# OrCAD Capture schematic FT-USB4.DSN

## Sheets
1 INDEX: title: 01-INDEX; rev: 1.0
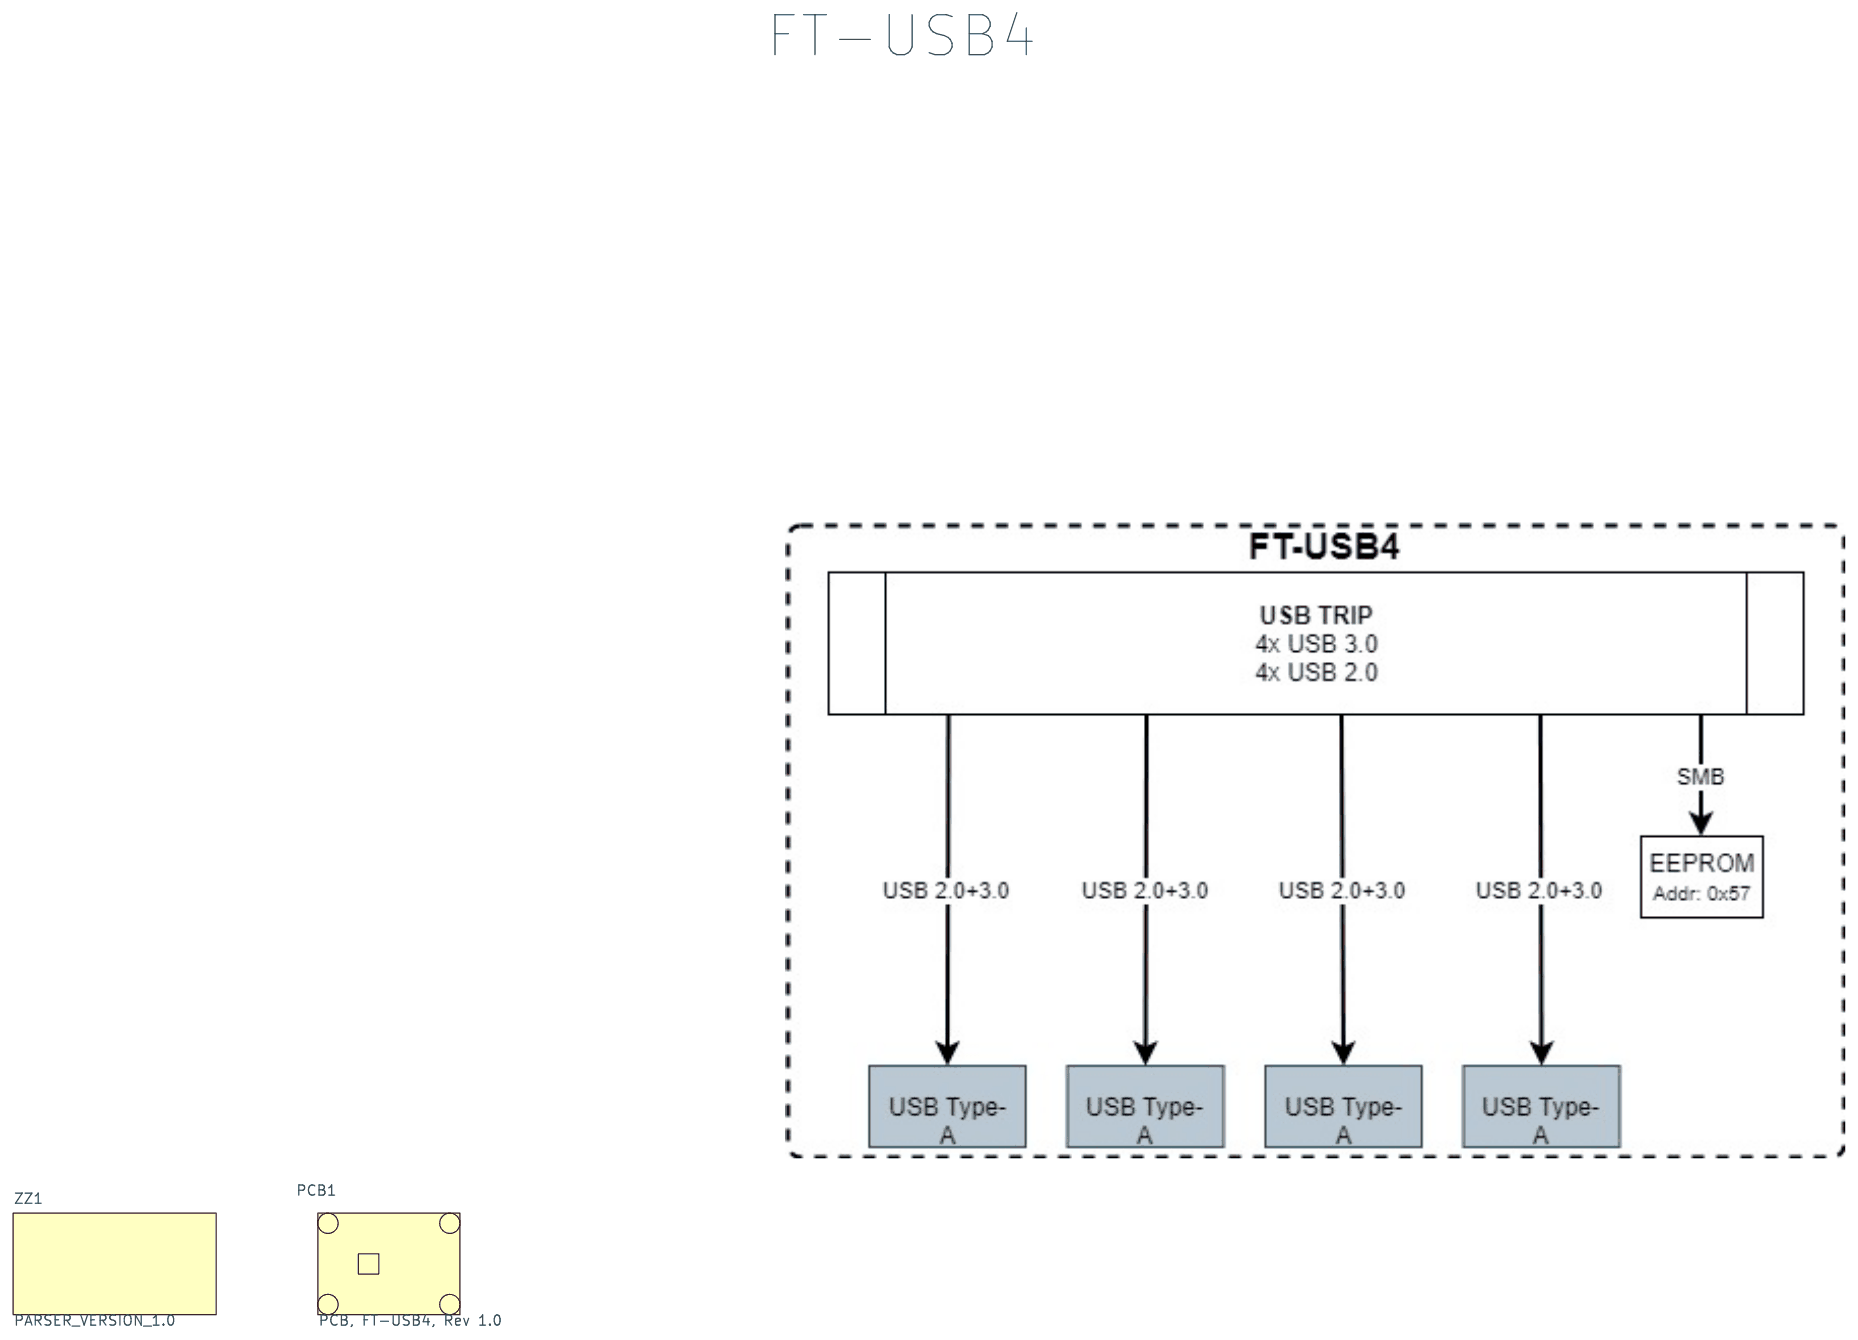
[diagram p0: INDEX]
2 TRIP: size A; title: 02-TRIP
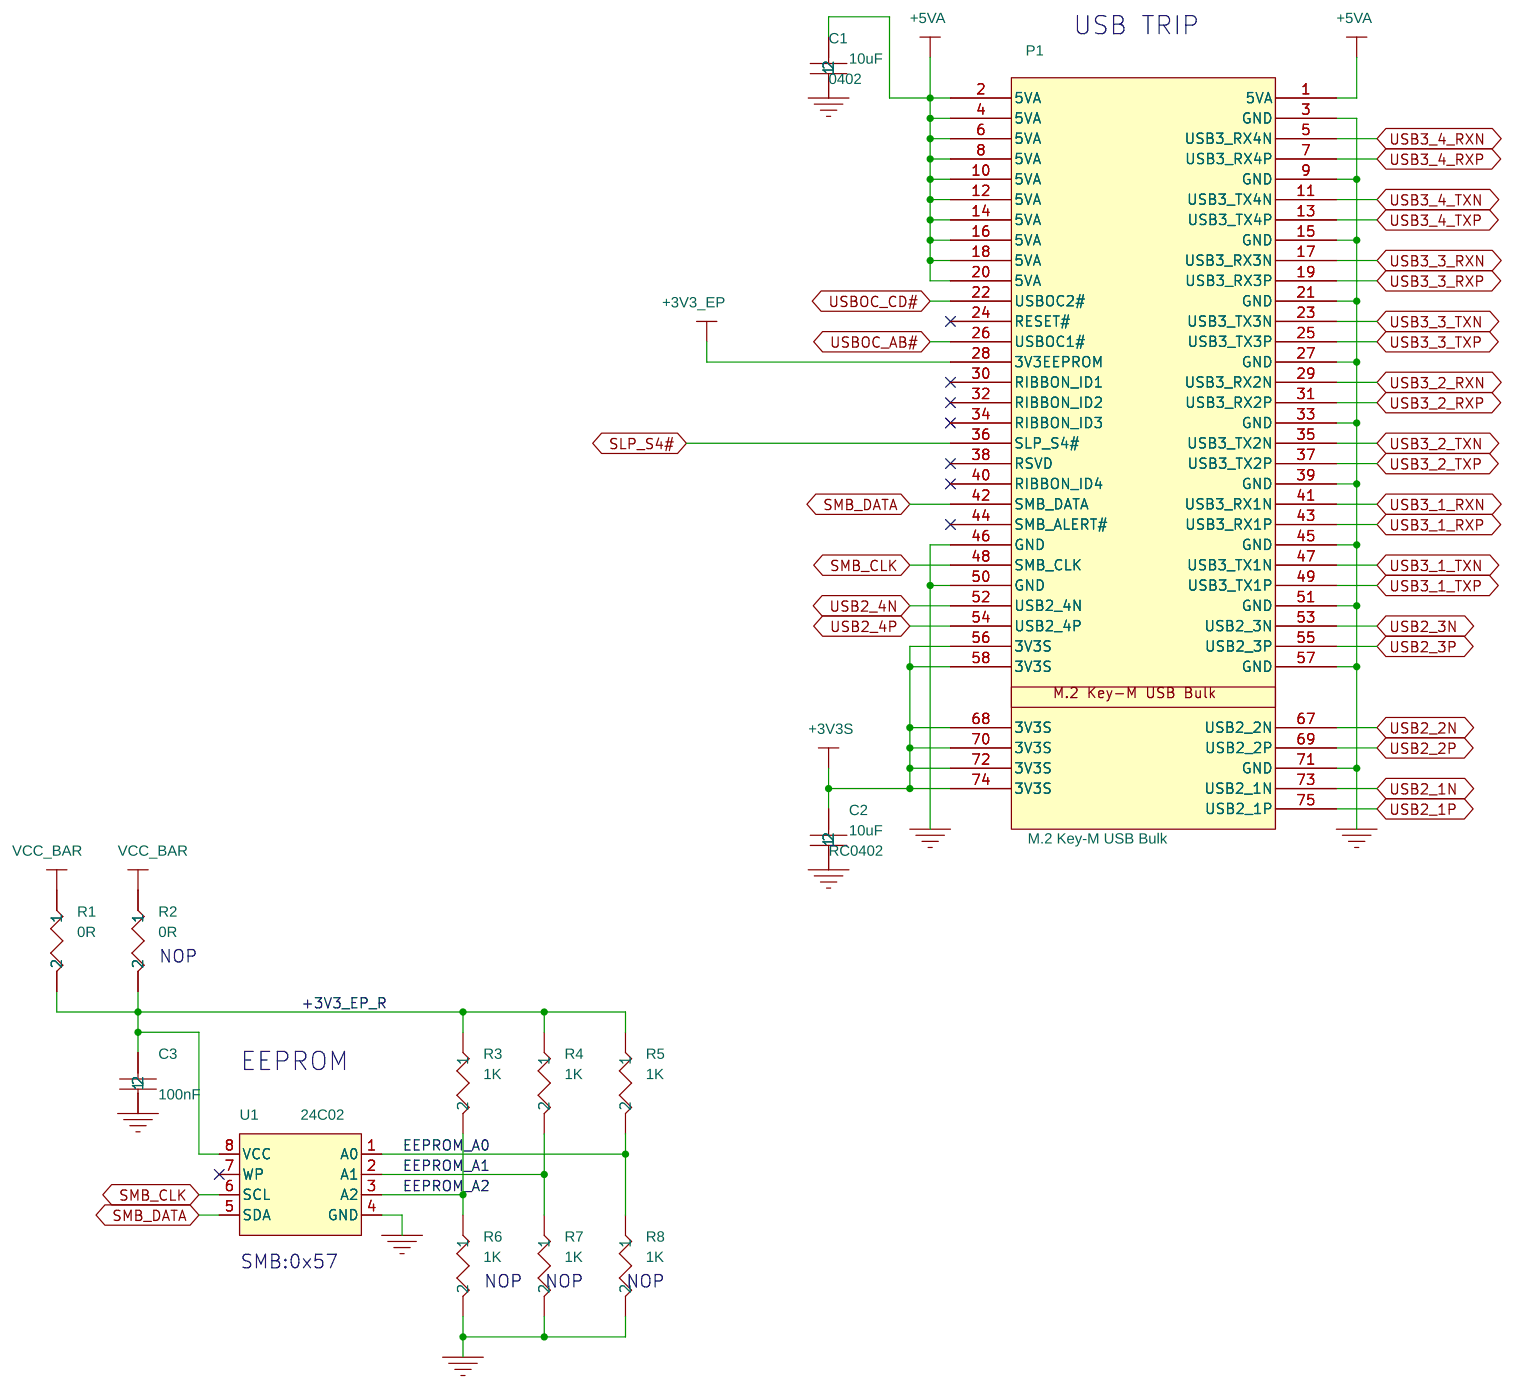
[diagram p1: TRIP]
3 USB: size A3; title: 03-USB
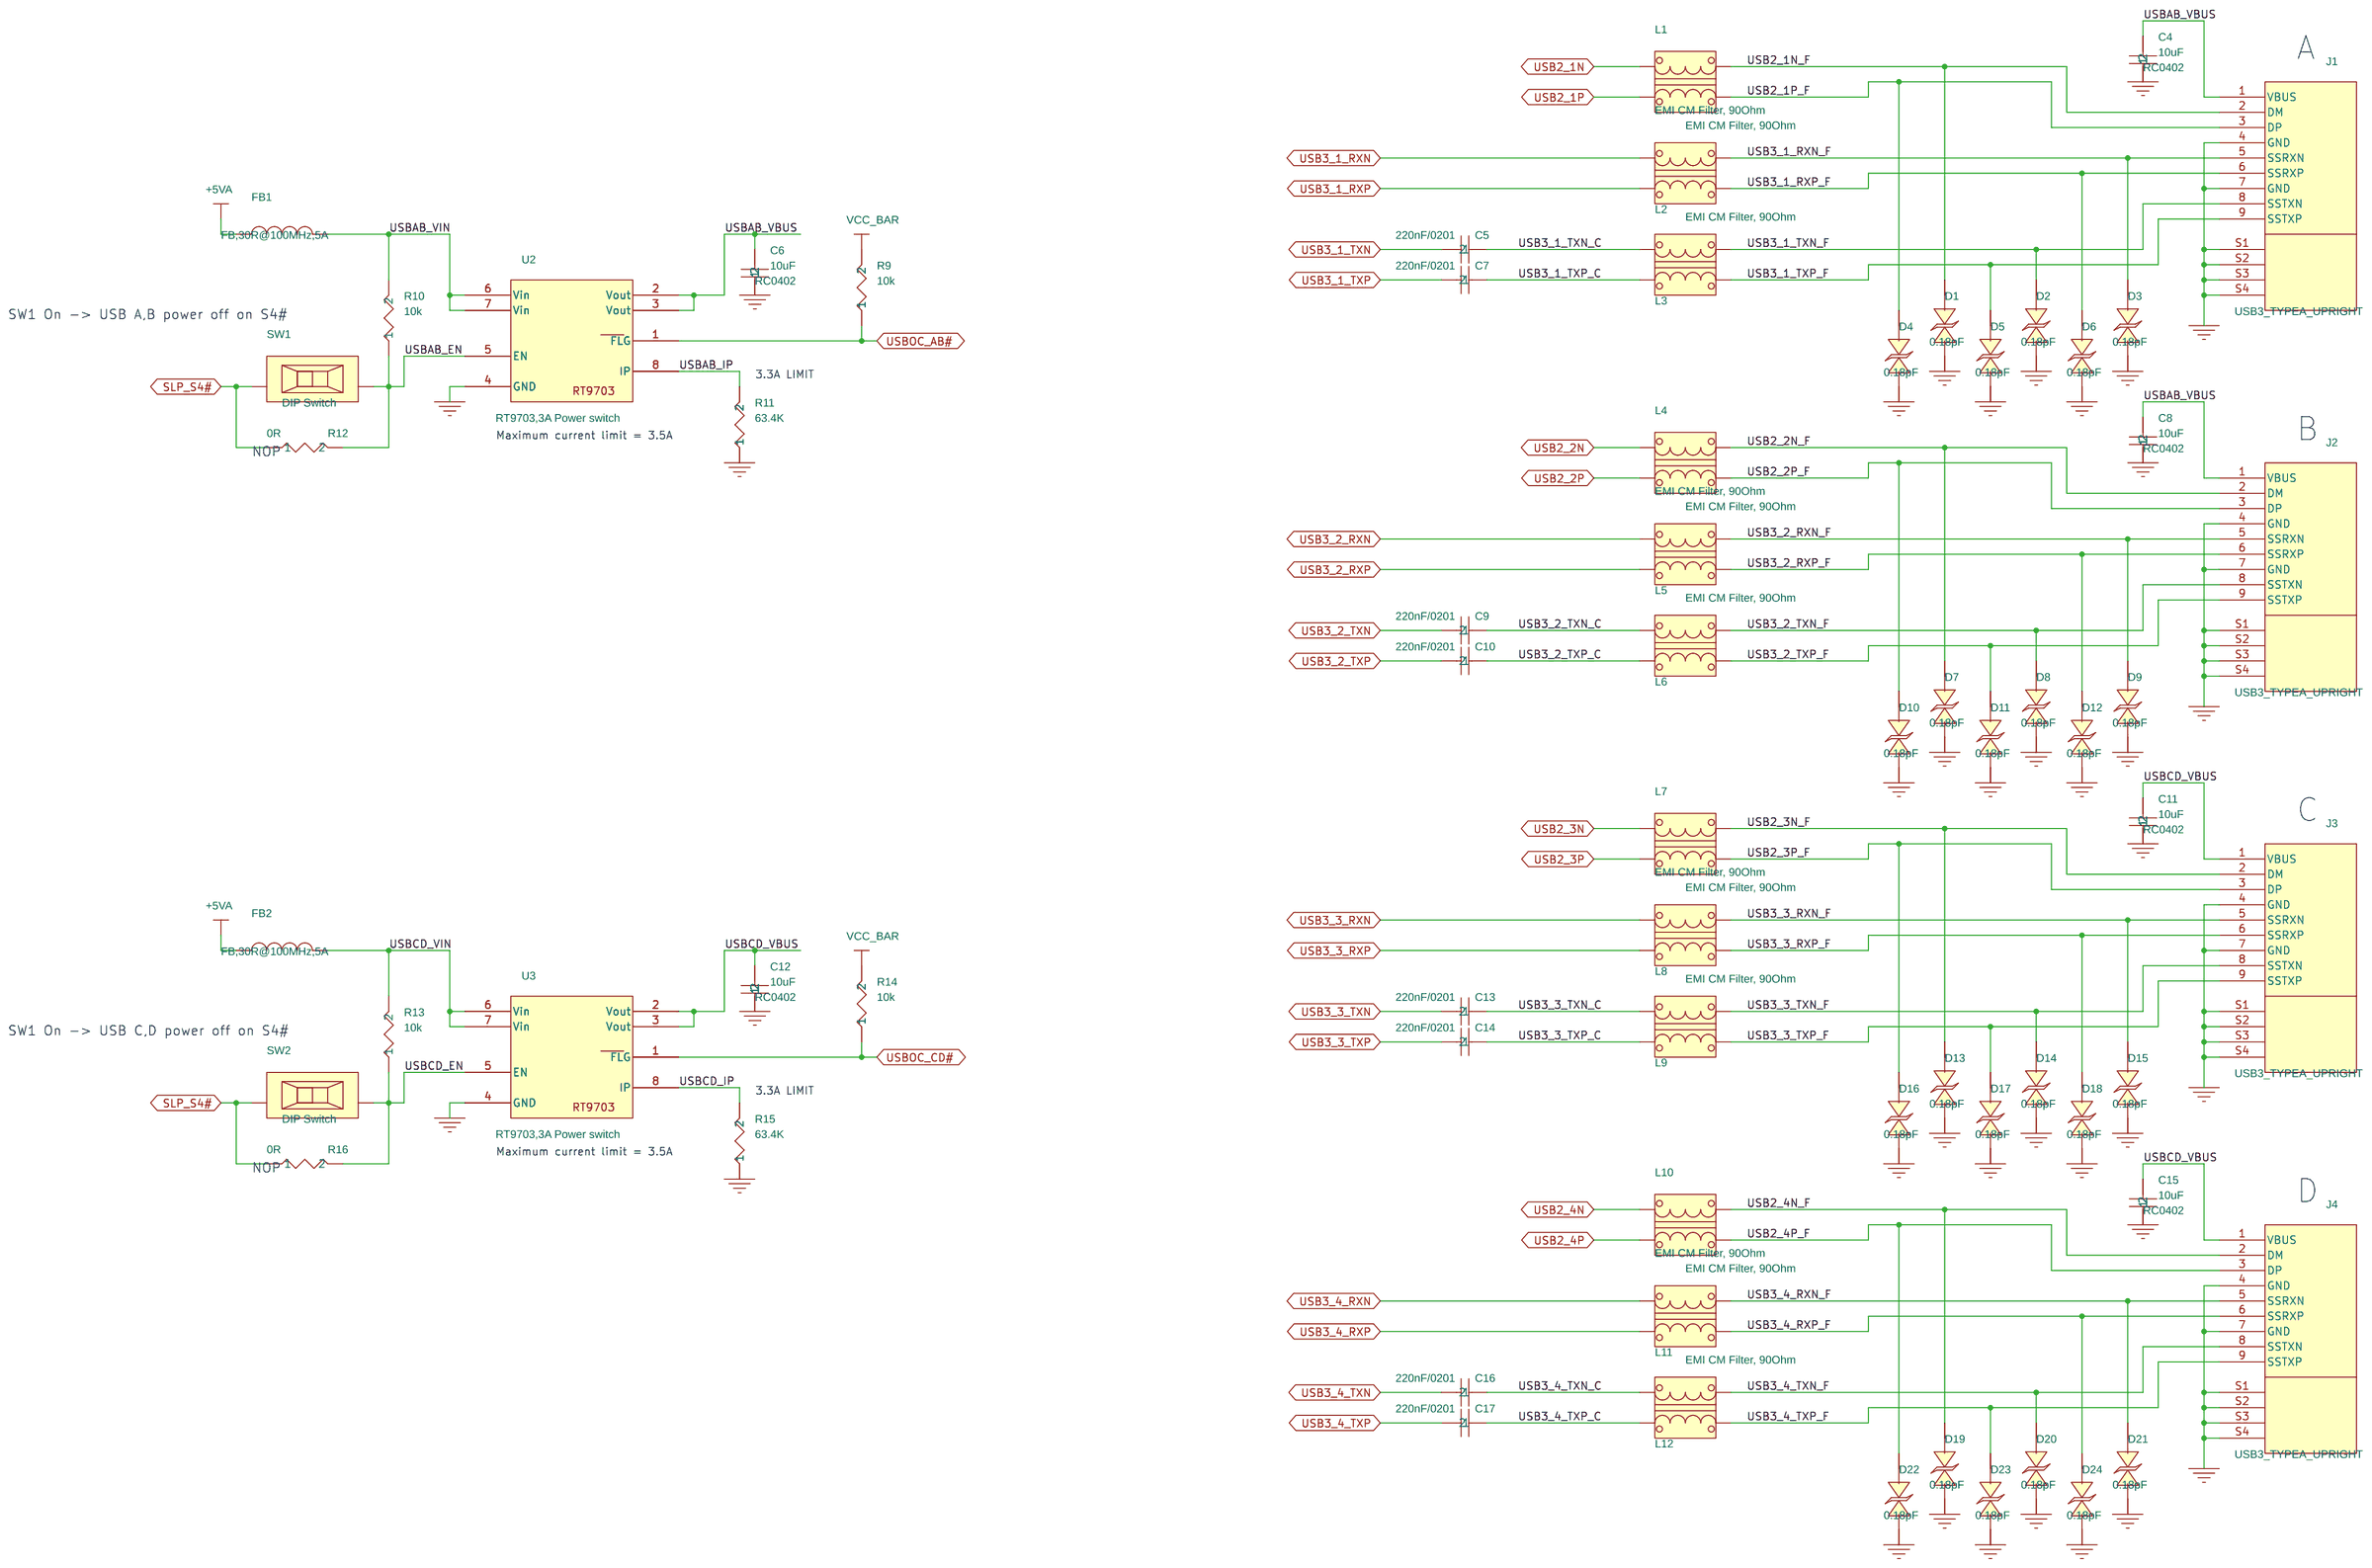
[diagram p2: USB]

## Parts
sheet INDEX
PCB1  PCB, FT-USB4, Rev 1.0
ZZ1  PARSER_VERSION_1.0
sheet TRIP
C1  10uF  [0402]
C2  10uF  [RC0402]
C3  100nF  [RC0402]
P1  M.2 Key-M USB Bulk  [NGFF67P8HMkeySM]
R1  0R  [RC0402]
R2  0R  [RC0402]
R3  1K  [RC0402]
R4  1K  [RC0402]
R5  1K  [RC0402]
R6  1K  [RC0402]
R7  1K  [RC0402]
R8  1K  [RC0402]
U1  24C02  [MO-229VCED-2]
sheet USB
C4  10uF  [RC0402]
C5  220nF/0201  [RC0201]
C6  10uF  [RC0402]
C7  220nF/0201  [RC0402]
C8  10uF  [RC0402]
C9  220nF/0201  [RC0201]
C10  220nF/0201  [RC0402]
C11  10uF  [RC0402]
C12  10uF  [RC0402]
C13  220nF/0201  [RC0201]
C14  220nF/0201  [RC0402]
C15  10uF  [RC0402]
C16  220nF/0201  [RC0201]
C17  220nF/0201  [RC0402]
D1  0.18pF  [RC0201]
D2  0.18pF  [RC0201]
D3  0.18pF  [RC0201]
D4  0.18pF  [RC0201]
D5  0.18pF  [RC0201]
D6  0.18pF  [RC0201]
D7  0.18pF  [RC0201]
D8  0.18pF  [RC0201]
D9  0.18pF  [RC0201]
D10  0.18pF  [RC0201]
D11  0.18pF  [RC0201]
D12  0.18pF  [RC0201]
D13  0.18pF  [RC0201]
D14  0.18pF  [RC0201]
D15  0.18pF  [RC0201]
D16  0.18pF  [RC0201]
D17  0.18pF  [RC0201]
D18  0.18pF  [RC0201]
D19  0.18pF  [RC0201]
D20  0.18pF  [RC0201]
D21  0.18pF  [RC0201]
D22  0.18pF  [RC0201]
D23  0.18pF  [RC0201]
D24  0.18pF  [RC0201]
FB1  FB,30R@100MHz,5A  [FB0603]
FB2  FB,30R@100MHz,5A  [FB0603]
J1  USB3_TYPEA_UPRIGHT  [USB3_TYPEA]
J2  USB3_TYPEA_UPRIGHT  [USB3_TYPEA]
J3  USB3_TYPEA_UPRIGHT  [USB3_TYPEA]
J4  USB3_TYPEA_UPRIGHT  [USB3_TYPEA]
L1  EMI CM Filter, 90Ohm  [EMI1012]
L2  EMI CM Filter, 90Ohm  [EMI1012]
L3  EMI CM Filter, 90Ohm  [EMI1012]
L4  EMI CM Filter, 90Ohm  [EMI1012]
L5  EMI CM Filter, 90Ohm  [EMI1012]
L6  EMI CM Filter, 90Ohm  [EMI1012]
L7  EMI CM Filter, 90Ohm  [EMI1012]
L8  EMI CM Filter, 90Ohm  [EMI1012]
L9  EMI CM Filter, 90Ohm  [EMI1012]
L10  EMI CM Filter, 90Ohm  [EMI1012]
L11  EMI CM Filter, 90Ohm  [EMI1012]
L12  EMI CM Filter, 90Ohm  [EMI1012]
R9  10k  [RC0402]
R10  10k  [RC0402]
R11  63.4K  [RC0402]
R12  0R  [RC0402]
R13  10k  [RC0402]
R14  10k  [RC0402]
R15  63.4K  [RC0402]
R16  0R  [RC0402]
SW1  DIP Switch  [SWDIP-1SM]
SW2  DIP Switch  [SWDIP-1SM]
U2  RT9703,3A Power switch  [SO-8-150]
U3  RT9703,3A Power switch  [SO-8-150]

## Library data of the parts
PCB1 = SBC-iHSW_Rev_1.0: CLABCONF0: FT.E-USB4; P/N: 188C03370
ZZ1 = PARSER_VERSION_1.0: CLABCONF0: FT.E-USB4
C1 C15 = 100nF,_10V,_X7R,_10%,_0402_1: CLABCONF0: FT.E-USB4; P/N: 151B10600S
C2 C4 = 100nF,_10V,_X7R,_10%,_0402: CLABCONF0: FT.E-USB4; P/N: 151B10600S
C3 = 15pF,_50V,_NPO,_5%,_0402: CLABCONF0: FT.E-USB4; P/N: 151B10400S
P1 = M.2_Key-M_USB_Bulk: CLABCONF0: FT.E-USB4; P/N: 182K06700S
R1 = 348R,1%,0402,1_16W_5: CLABCONF0: FT.E-USB4; P/N: 161C00005S
R2 = 348R,1%,0402,1_16W_6: CLABCONF0: NOP; P/N: 161C00005S
R3 = 348R,1%,0402,1_16W_3: CLABCONF0: FT.E-USB4; P/N: 161C10011S
R4 = 348R,1%,0402,1_16W_7: CLABCONF0: FT.E-USB4; P/N: 161C10011S
R5 = 348R,1%,0402,1_16W_4: CLABCONF0: FT.E-USB4; P/N: 161C10011S
R6 = 348R,1%,0402,1_16W_1: CLABCONF0: NOP; P/N: 161C10011S
R7 = 348R,1%,0402,1_16W: CLABCONF0: NOP; P/N: 161C10011S
R8 = 348R,1%,0402,1_16W_2: CLABCONF0: NOP; P/N: 161C10011S
U1 = 24C02,_serial_EE,_2KB,_I2C: CLABCONF0: FT.E-USB4; P/N: 111S30801S
C5 = 100nF,_10V,_X7R,_10%,_0402_3: CLABCONF0: FT.E-USB4; P/N: 151C224B0S
C6 = 100nF,_10V,_X7R,_10%,_0402_6: CLABCONF0: FT.E-USB4; P/N: 151B10600S
C7 = 100nF,_10V,_X7R,_10%,_0402_5: CLABCONF0: FT.E-USB4; P/N: 151C224B0S
C8 = 100nF,_10V,_X7R,_10%,_0402_11: CLABCONF0: FT.E-USB4; P/N: 151B10600S
C9 = 100nF,_10V,_X7R,_10%,_0402_4: CLABCONF0: FT.E-USB4; P/N: 151C224B0S
C10 = 100nF,_10V,_X7R,_10%,_0402_8: CLABCONF0: FT.E-USB4; P/N: 151C224B0S
C11 = 100nF,_10V,_X7R,_10%,_0402_12: CLABCONF0: FT.E-USB4; P/N: 151B10600S
C12 = 100nF,_10V,_X7R,_10%,_0402_2: CLABCONF0: FT.E-USB4; P/N: 151B10600S
C13 = 100nF,_10V,_X7R,_10%,_0402_7: CLABCONF0: FT.E-USB4; P/N: 151C224B0S
C14 = 100nF,_10V,_X7R,_10%,_0402_9: CLABCONF0: FT.E-USB4; P/N: 151C224B0S
C16 = 100nF,_10V,_X7R,_10%,_0402_10: CLABCONF0: FT.E-USB4; P/N: 151C224B0S
C17 = 100nF,_10V,_X7R,_10%,_0402_13: CLABCONF0: FT.E-USB4; P/N: 151C224B0S
D1-D24 = DIODE_TVS_BI-DIR: CLABCONF0: FT.E-USB4; P/N: 132D10070S
FB1 = Ferrite_bead_,_120_Ohm@3A: CLABCONF0: FT.E-USB4; P/N: 147D30000S
FB2 = Ferrite_bead_,_120_Ohm@3A_1: CLABCONF0: FT.E-USB4; P/N: 147D30000S
J1-J4 = USB3_TYPEA_CONNECTER_1: CLABCONF0: FT.E-USB4; P/N: 180K00903; PART_NUMBER: DS PORT2
L1-L12 = Murata_DLP11SN900SL2_0: CLABCONF0: FT.E-USB4
R9 = 1M_,5%,_0402_4: CLABCONF0: FT.E-USB4; P/N: 161C10021S
R10 = 1M_,5%,_0402: CLABCONF0: FT.E-USB4; P/N: 161C10021S
R11 = 1M_,5%,_0402_3: CLABCONF0: FT.E-USB4; P/N: 161C63421S
R12 = 0R_1: CLABCONF0: NOP
R13 = 1M_,5%,_0402_5: CLABCONF0: FT.E-USB4; P/N: 161C10021S
R14 = 1M_,5%,_0402_1: CLABCONF0: FT.E-USB4; P/N: 161C10021S
R15 = 1M_,5%,_0402_2: CLABCONF0: FT.E-USB4; P/N: 161C63421S
R16 = 0R: CLABCONF0: NOP
SW1 SW2 = SW_DIP_Switch_x1: CLABCONF0: FT.E-USB4; P/N: 170I30100S
U2 U3 = RT9703,3A_Power_switch+FLG: CLABCONF0: FT.E-USB4

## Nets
+3V3_EP: P1.28(3V3EEPROM) R1.1
+3V3_EP_R: C3.2 R1.2 R2.2 R3.1 R4.1 R5.1 U1.8(VCC)
+3V3S: C2.2 P1.56(3V3S) P1.58(3V3S) P1.68(3V3S) P1.70(3V3S) P1.72(3V3S) P1.74(3V3S) R2.1 R9.2 R14.2
+5VA: C1.2 FB1.1 FB2.1 P1.1(5VA) P1.2(5VA) P1.4(5VA) P1.6(5VA) P1.8(5VA) P1.10(5VA) P1.12(5VA) P1.14(5VA) P1.16(5VA) P1.18(5VA) P1.20(5VA)
GND: C1.1 C2.1 C3.1 C4.1 C6.1 C8.1 C11.1 C12.1 C15.1 D1.1 D2.1 D3.1 D4.1 D5.1 D6.1 D7.1 D8.1 D9.1 D10.1 D11.1 D12.1 D13.1 D14.1 D15.1 D16.1 D17.1 D18.1 D19.1 D20.1 D21.1 D22.1 D23.1 D24.1 J1.4(GND) J1.7(GND) J1.S1 J1.S2 J1.S3 J1.S4 J2.4(GND) J2.7(GND) J2.S1 J2.S2 J2.S3 J2.S4 J3.4(GND) J3.7(GND) J3.S1 J3.S2 J3.S3 J3.S4 J4.4(GND) J4.7(GND) J4.S1 J4.S2 J4.S3 J4.S4 P1.3(GND) P1.9(GND) P1.15(GND) P1.21(GND) P1.27(GND) P1.33(GND) P1.39(GND) P1.45(GND) P1.46(GND) P1.50(GND) P1.51(GND) P1.57(GND) P1.71(GND) R6.2 R7.2 R8.2 R11.1 R15.1 U1.4(GND) U2.4(GND) U3.4(GND)
EEPROM_A0: R5.2 R8.1 U1.1(A0)
EEPROM_A1: R4.2 R7.1 U1.2(A1)
EEPROM_A2: R3.2 R6.1 U1.3(A2)
SLP_S4#: P1.36(SLP_S4#) R12.1 R16.1 SW1.1 SW2.1
SMB_CLK: P1.48(SMB_CLK) U1.6(SCL)
SMB_DATA: P1.42(SMB_DATA) U1.5(SDA)
USB2_1N: L1.3 P1.73(USB2_1N)
USB2_1N_F: D1.2 J1.2(DM) L1.2
USB2_1P: L1.4 P1.75(USB2_1P)
USB2_1P_F: D4.2 J1.3(DP) L1.1
USB2_2N: L4.3 P1.67(USB2_2N)
USB2_2N_F: D7.2 J2.2(DM) L4.2
USB2_2P: L4.4 P1.69(USB2_2P)
USB2_2P_F: D10.2 J2.3(DP) L4.1
USB2_3N: L7.3 P1.53(USB2_3N)
USB2_3N_F: D13.2 J3.2(DM) L7.2
USB2_3P: L7.4 P1.55(USB2_3P)
USB2_3P_F: D16.2 J3.3(DP) L7.1
USB2_4N: L10.3 P1.52(USB2_4N)
USB2_4N_F: D19.2 J4.2(DM) L10.2
USB2_4P: L10.4 P1.54(USB2_4P)
USB2_4P_F: D22.2 J4.3(DP) L10.1
USB3_1_RXN: L2.4 P1.41(USB3_RX1N)
USB3_1_RXN_F: D3.2 J1.5(SSRXN) L2.1
USB3_1_RXP: L2.3 P1.43(USB3_RX1P)
USB3_1_RXP_F: D6.2 J1.6(SSRXP) L2.2
USB3_1_TXN: C5.2 P1.47(USB3_TX1N)
USB3_1_TXN_C: C5.1 L3.4
USB3_1_TXN_F: D2.2 J1.8(SSTXN) L3.1
USB3_1_TXP: C7.2 P1.49(USB3_TX1P)
USB3_1_TXP_C: C7.1 L3.3
USB3_1_TXP_F: D5.2 J1.9(SSTXP) L3.2
USB3_2_RXN: L5.4 P1.29(USB3_RX2N)
USB3_2_RXN_F: D9.2 J2.5(SSRXN) L5.1
USB3_2_RXP: L5.3 P1.31(USB3_RX2P)
USB3_2_RXP_F: D12.2 J2.6(SSRXP) L5.2
USB3_2_TXN: C9.2 P1.35(USB3_TX2N)
USB3_2_TXN_C: C9.1 L6.4
USB3_2_TXN_F: D8.2 J2.8(SSTXN) L6.1
USB3_2_TXP: C10.2 P1.37(USB3_TX2P)
USB3_2_TXP_C: C10.1 L6.3
USB3_2_TXP_F: D11.2 J2.9(SSTXP) L6.2
USB3_3_RXN: L8.4 P1.17(USB3_RX3N)
USB3_3_RXN_F: D15.2 J3.5(SSRXN) L8.1
USB3_3_RXP: L8.3 P1.19(USB3_RX3P)
USB3_3_RXP_F: D18.2 J3.6(SSRXP) L8.2
USB3_3_TXN: C13.2 P1.23(USB3_TX3N)
USB3_3_TXN_C: C13.1 L9.4
USB3_3_TXN_F: D14.2 J3.8(SSTXN) L9.1
USB3_3_TXP: C14.2 P1.25(USB3_TX3P)
USB3_3_TXP_C: C14.1 L9.3
USB3_3_TXP_F: D17.2 J3.9(SSTXP) L9.2
USB3_4_RXN: L11.4 P1.5(USB3_RX4N)
USB3_4_RXN_F: D21.2 J4.5(SSRXN) L11.1
USB3_4_RXP: L11.3 P1.7(USB3_RX4P)
USB3_4_RXP_F: D24.2 J4.6(SSRXP) L11.2
USB3_4_TXN: C16.2 P1.11(USB3_TX4N)
USB3_4_TXN_C: C16.1 L12.4
USB3_4_TXN_F: D20.2 J4.8(SSTXN) L12.1
USB3_4_TXP: C17.2 P1.13(USB3_TX4P)
USB3_4_TXP_C: C17.1 L12.3
USB3_4_TXP_F: D23.2 J4.9(SSTXP) L12.2
USBAB_EN: R10.1 R12.2 SW1.2 U2.5(EN)
USBAB_IP: R11.2 U2.8(IP)
USBAB_VBUS: C4.2 C6.2 C8.2 J1.1(VBUS) J2.1(VBUS) U2.2(Vout) U2.3(Vout)
USBAB_VIN: FB1.2 R10.2 U2.6(Vin) U2.7(Vin)
USBCD_EN: R13.1 R16.2 SW2.2 U3.5(EN)
USBCD_IP: R15.2 U3.8(IP)
USBCD_VBUS: C11.2 C12.2 C15.2 J3.1(VBUS) J4.1(VBUS) U3.2(Vout) U3.3(Vout)
USBCD_VIN: FB2.2 R13.2 U3.6(Vin) U3.7(Vin)
USBOC_AB#: P1.26(USBOC1#) R9.1 U2.1(FLG)
USBOC_CD#: P1.22(USBOC2#) R14.1 U3.1(FLG)

Not connected (* = marked no-connect by the designer): P1 24(RESET#)* 30(RIBBON_ID1)* 32(RIBBON_ID2)* 34(RIBBON_ID3)* 38(RSVD)* 40(RIBBON_ID4)* 44(SMB_ALERT#)*; U1 7(WP)*

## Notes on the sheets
sheet 1
- FT-USB4
sheet 2
- USB TRIP
- NOP
- EEPROM
- SMB:0x57
- NOP
- NOP
- NOP
sheet 3
- A
- SW1 On -> USB A,B power off on S4#
- 3.3A LIMIT
- B
- Maximum current limit = 3.5A
- NOP
- C
- SW1 On -> USB C,D power off on S4#
- 3.3A LIMIT
- Maximum current limit = 3.5A
- NOP
- D
